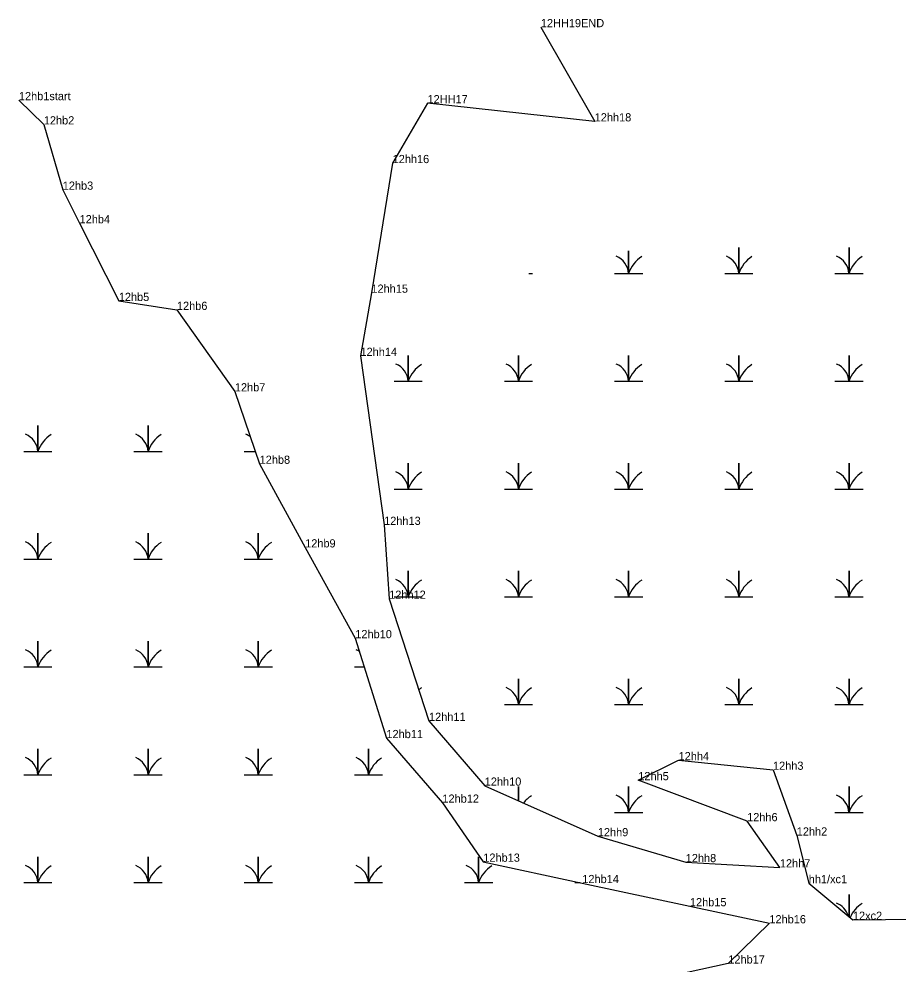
# Model space of a CAD drawing. Extents: x 2072529 to 2268796, y 436423 to 470397.
# Drawn here: x 2229917 to 2230453, y 451533 to 452110 of the extents above; entities that cross this region are included whole.
import ezdxf

# ---------------------------------------------------------------- set-up
doc = ezdxf.new("R2010")
doc.units = 0
for name, color, linetype in [('Exist Environmental Wetland Boundary', 7, 'Continuous'), ('Exist Environmental Wetland Boundary Cogo Comment', 7, 'Continuous'), ('Exist Environmental Wetland Boundary Cogo Point CELL', 7, 'Continuous'), ('Exist Hydro Swamp or Marsh', 7, 'Continuous')]:
    doc.layers.add(name, color=color, linetype=linetype)

msp = doc.modelspace()

# ---------------------------------------------------------------- linework, layer by layer
at = {"layer": 'Exist Environmental Wetland Boundary'}
for points in [[(2230235.08, 452104.53), (2230267.96, 452047.04), (2230165.91, 452058.11), (2230144.64, 452021.59), (2230131.69, 451942.48), (2230125.01, 451903.92), (2230139.43, 451800.78), (2230142.52, 451755.69), (2230166.82, 451681.15), (2230200.84, 451641.63), (2230269.85, 451610.77), (2230323.51, 451594.95), (2230380.96, 451591.75), (2230360.97, 451619.93), (2230294.56, 451644.97), (2230319.15, 451657.16), (2230376.77, 451651.31), (2230391.27, 451611.19), (2230398.58, 451582.1), (2230425.55, 451559.76), (2230485.18, 451560.46)], [(2229916.54, 452059.99), (2229931.73, 452045.2), (2229943.3, 452005.34), (2229953.58, 451984.88), (2229977.5, 451937.44), (2230012.98, 451931.99), (2230048.35, 451882.27), (2230063.46, 451838.07), (2230091.25, 451787.04), (2230121.85, 451731.65), (2230140.84, 451670.66), (2230175.01, 451631.24), (2230199.96, 451595.2), (2230260.4, 451582.17), (2230326.07, 451568.04), (2230374.56, 451557.62), (2230349.49, 451533.09), (2230284.51, 451518.88), (2230215.75, 451507.19), (2230145.13, 451476.98), (2230150.38, 451444.23)]]:
    msp.add_lwpolyline(points, dxfattribs=at)
at = {"layer": 'Exist Environmental Wetland Boundary Cogo Point CELL'}
for p, q in [((2230235.08, 452104.53), (2230235.08, 452104.53)), ((2229916.54, 452059.99), (2229916.54, 452059.99)), ((2230165.91, 452058.11), (2230165.91, 452058.11)), ((2229931.73, 452045.2), (2229931.73, 452045.2)), ((2230267.96, 452047.04), (2230267.96, 452047.04)), ((2230144.64, 452021.59), (2230144.64, 452021.59)), ((2229943.3, 452005.34), (2229943.3, 452005.34)), ((2229953.58, 451984.88), (2229953.58, 451984.88)), ((2229977.5, 451937.44), (2229977.5, 451937.44)), ((2230012.98, 451931.99), (2230012.98, 451931.99)), ((2230125.01, 451903.92), (2230125.01, 451903.92)), ((2230048.35, 451882.27), (2230048.35, 451882.27)), ((2230063.46, 451838.07), (2230063.46, 451838.07)), ((2230139.43, 451800.78), (2230139.43, 451800.78)), ((2230091.25, 451787.04), (2230091.25, 451787.04)), ((2230142.52, 451755.69), (2230142.52, 451755.69)), ((2230121.85, 451731.65), (2230121.85, 451731.65)), ((2230166.82, 451681.15), (2230166.82, 451681.15)), ((2230140.84, 451670.66), (2230140.84, 451670.66)), ((2230319.15, 451657.16), (2230319.15, 451657.16)), ((2230376.77, 451651.31), (2230376.77, 451651.31)), ((2230200.84, 451641.63), (2230200.84, 451641.63)), ((2230294.56, 451644.97), (2230294.56, 451644.97)), ((2230175.01, 451631.24), (2230175.01, 451631.24)), ((2230360.97, 451619.93), (2230360.97, 451619.93)), ((2230269.85, 451610.77), (2230269.85, 451610.77)), ((2230391.27, 451611.19), (2230391.27, 451611.19)), ((2230199.96, 451595.2), (2230199.96, 451595.2)), ((2230323.51, 451594.95), (2230323.51, 451594.95)), ((2230380.96, 451591.75), (2230380.96, 451591.75)), ((2230260.4, 451582.17), (2230260.4, 451582.17)), ((2230398.58, 451582.1), (2230398.58, 451582.1)), ((2230326.07, 451568.04), (2230326.07, 451568.04)), ((2230425.55, 451559.76), (2230425.55, 451559.76)), ((2230374.56, 451557.62), (2230374.56, 451557.62)), ((2230349.49, 451533.09), (2230349.49, 451533.09))]:
    msp.add_line(p, q, dxfattribs=at)
at = {"layer": 'Exist Hydro Swamp or Marsh'}
for points in [[(2230347.3, 451954.29), (2230355.9, 451954.29), (2230355.9, 451970.07), (2230355.9, 451954.29), (2230364.5, 451954.29)], [(2230414.55, 451954.29), (2230423.15, 451954.29), (2230423.15, 451970.07), (2230423.15, 451954.29), (2230431.75, 451954.29)], [(2230280.05, 451954.29), (2230288.65, 451954.29), (2230288.65, 451968.01)], [(2230288.65, 451968.01), (2230288.65, 451954.29), (2230297.25, 451954.29)], [(2230227.81, 451954.29), (2230230, 451954.29)], [(2230145.55, 451888.49), (2230154.15, 451888.49), (2230154.15, 451904.27), (2230154.15, 451888.49), (2230162.75, 451888.49)], [(2230212.8, 451888.49), (2230221.4, 451888.49), (2230221.4, 451904.27), (2230221.4, 451888.49), (2230230, 451888.49)], [(2230280.05, 451888.49), (2230288.65, 451888.49), (2230288.65, 451904.27), (2230288.65, 451888.49), (2230297.25, 451888.49)], [(2230347.3, 451888.49), (2230355.9, 451888.49), (2230355.9, 451904.27), (2230355.9, 451888.49), (2230364.5, 451888.49)], [(2230414.55, 451888.49), (2230423.15, 451888.49), (2230423.15, 451904.27), (2230423.15, 451888.49), (2230431.75, 451888.49)], [(2229919.53, 451845.68), (2229928.13, 451845.68), (2229928.13, 451861.46), (2229928.13, 451845.68), (2229936.73, 451845.68)], [(2229986.78, 451845.68), (2229995.38, 451845.68), (2229995.38, 451861.46), (2229995.38, 451845.68), (2230003.98, 451845.68)], [(2230054.03, 451845.68), (2230060.86, 451845.68)], [(2230145.55, 451822.69), (2230154.15, 451822.69), (2230154.15, 451838.47), (2230154.15, 451822.69), (2230162.75, 451822.69)], [(2230212.8, 451822.69), (2230221.4, 451822.69), (2230221.4, 451838.47), (2230221.4, 451822.69), (2230230, 451822.69)], [(2230280.05, 451822.69), (2230288.65, 451822.69), (2230288.65, 451838.47), (2230288.65, 451822.69), (2230297.25, 451822.69)], [(2230347.3, 451822.69), (2230355.9, 451822.69), (2230355.9, 451838.47), (2230355.9, 451822.69), (2230364.5, 451822.69)], [(2230414.55, 451822.69), (2230423.15, 451822.69), (2230423.15, 451838.47), (2230423.15, 451822.69), (2230431.75, 451822.69)], [(2229919.53, 451779.88), (2229928.13, 451779.88), (2229928.13, 451795.66), (2229928.13, 451779.88), (2229936.73, 451779.88)], [(2229986.78, 451779.88), (2229995.38, 451779.88), (2229995.38, 451795.66), (2229995.38, 451779.88), (2230003.98, 451779.88)], [(2230054.03, 451779.88), (2230062.63, 451779.88), (2230062.63, 451795.66), (2230062.63, 451779.88), (2230071.23, 451779.88)], [(2230145.55, 451756.89), (2230154.15, 451756.89), (2230154.15, 451772.67), (2230154.15, 451756.89), (2230162.75, 451756.89)], [(2230212.8, 451756.89), (2230221.4, 451756.89), (2230221.4, 451772.67), (2230221.4, 451756.89), (2230230, 451756.89)], [(2230280.05, 451756.89), (2230288.65, 451756.89), (2230288.65, 451772.67), (2230288.65, 451756.89), (2230297.25, 451756.89)], [(2230347.3, 451756.89), (2230355.9, 451756.89), (2230355.9, 451772.67), (2230355.9, 451756.89), (2230364.5, 451756.89)], [(2230414.55, 451756.89), (2230423.15, 451756.89), (2230423.15, 451772.67), (2230423.15, 451756.89), (2230431.75, 451756.89)], [(2229919.53, 451714.08), (2229928.13, 451714.08), (2229928.13, 451729.86), (2229928.13, 451714.08), (2229936.73, 451714.08)], [(2229986.78, 451714.08), (2229995.38, 451714.08), (2229995.38, 451729.86), (2229995.38, 451714.08), (2230003.98, 451714.08)], [(2230054.03, 451714.08), (2230062.63, 451714.08), (2230062.63, 451729.86), (2230062.63, 451714.08), (2230071.23, 451714.08)], [(2230121.28, 451714.08), (2230127.32, 451714.08)], [(2230212.8, 451691.09), (2230221.4, 451691.09), (2230221.4, 451706.87), (2230221.4, 451691.09), (2230230, 451691.09)], [(2230280.05, 451691.09), (2230288.65, 451691.09), (2230288.65, 451706.87), (2230288.65, 451691.09), (2230297.25, 451691.09)], [(2230347.3, 451691.09), (2230355.9, 451691.09), (2230355.9, 451706.87), (2230355.9, 451691.09), (2230364.5, 451691.09)], [(2230414.55, 451691.09), (2230423.15, 451691.09), (2230423.15, 451706.87), (2230423.15, 451691.09), (2230431.75, 451691.09)], [(2229919.53, 451648.28), (2229928.13, 451648.28), (2229928.13, 451664.06), (2229928.13, 451648.28), (2229936.73, 451648.28)], [(2229986.78, 451648.28), (2229995.38, 451648.28), (2229995.38, 451664.06), (2229995.38, 451648.28), (2230003.98, 451648.28)], [(2230054.03, 451648.28), (2230062.63, 451648.28), (2230062.63, 451664.06), (2230062.63, 451648.28), (2230071.23, 451648.28)], [(2230121.28, 451648.28), (2230129.88, 451648.28), (2230129.88, 451664.06), (2230129.88, 451648.28), (2230138.48, 451648.28)], [(2230221.4, 451632.43), (2230221.4, 451641.07), (2230221.4, 451632.43)], [(2230280.05, 451625.29), (2230288.65, 451625.29), (2230288.65, 451641.07), (2230288.65, 451625.29), (2230297.25, 451625.29)], [(2230414.55, 451625.29), (2230423.15, 451625.29), (2230423.15, 451641.07), (2230423.15, 451625.29), (2230431.75, 451625.29)], [(2229919.53, 451582.48), (2229928.13, 451582.48), (2229928.13, 451598.26), (2229928.13, 451582.48), (2229936.73, 451582.48)], [(2229986.78, 451582.48), (2229995.38, 451582.48), (2229995.38, 451598.26), (2229995.38, 451582.48), (2230003.98, 451582.48)], [(2230054.03, 451582.48), (2230062.63, 451582.48), (2230062.63, 451598.26), (2230062.63, 451582.48), (2230071.23, 451582.48)], [(2230121.28, 451582.48), (2230129.88, 451582.48), (2230129.88, 451598.26), (2230129.88, 451582.48), (2230138.48, 451582.48)], [(2230188.53, 451582.48), (2230197.13, 451582.48), (2230197.13, 451598.26), (2230197.13, 451582.48), (2230205.73, 451582.48)], [(2230255.78, 451582.48), (2230258.99, 451582.48)], [(2230423.15, 451561.75), (2230423.15, 451575.27), (2230423.15, 451561.75)]]:
    msp.add_lwpolyline(points, dxfattribs=at)
for centre, radius, start, end in [((2230276.38, 451953.4), 12.3, 4.14034, 67.53497), ((2230306.89, 451948.23), 19.22, 122.12745, 161.62219), ((2230343.63, 451953.4), 12.3, 4.14034, 67.53497), ((2230374.14, 451948.23), 19.22, 122.12745, 161.62219), ((2230410.88, 451953.4), 12.3, 4.14034, 67.53497), ((2230441.39, 451948.23), 19.22, 122.12745, 161.62219), ((2230141.88, 451887.6), 12.3, 4.14034, 67.53497), ((2230172.39, 451882.43), 19.22, 122.12745, 161.62219), ((2230209.13, 451887.6), 12.3, 4.14034, 67.53497), ((2230239.64, 451882.43), 19.22, 122.12745, 161.62219), ((2230276.38, 451887.6), 12.3, 4.14034, 67.53497), ((2230306.89, 451882.43), 19.22, 122.12745, 161.62219), ((2230343.63, 451887.6), 12.3, 4.14034, 67.53497), ((2230374.14, 451882.43), 19.22, 122.12745, 161.62219), ((2230410.88, 451887.6), 12.3, 4.14034, 67.53497), ((2230441.39, 451882.43), 19.22, 122.12745, 161.62219), ((2229915.86, 451844.79), 12.3, 4.14034, 67.53497), ((2229946.37, 451839.62), 19.22, 122.12745, 161.62219), ((2229983.11, 451844.79), 12.3, 4.14034, 67.53497), ((2230013.62, 451839.62), 19.22, 122.12745, 161.62219), ((2230050.36, 451844.79), 12.3, 52.64789, 67.53497), ((2230141.88, 451821.8), 12.3, 4.14034, 67.53497), ((2230172.39, 451816.63), 19.22, 122.12745, 161.62219), ((2230209.13, 451821.8), 12.3, 4.14034, 67.53497), ((2230239.64, 451816.63), 19.22, 122.12745, 161.62219), ((2230276.38, 451821.8), 12.3, 4.14034, 67.53497), ((2230306.89, 451816.63), 19.22, 122.12745, 161.62219), ((2230343.63, 451821.8), 12.3, 4.14034, 67.53497), ((2230374.14, 451816.63), 19.22, 122.12745, 161.62219), ((2230410.88, 451821.8), 12.3, 4.14034, 67.53497), ((2230441.39, 451816.63), 19.22, 122.12745, 161.62219), ((2229915.86, 451778.99), 12.3, 4.14034, 67.53497), ((2229983.11, 451778.99), 12.3, 4.14034, 67.53497), ((2230050.36, 451778.99), 12.3, 4.14034, 67.53497), ((2229946.37, 451773.82), 19.22, 122.12745, 161.62219), ((2230013.62, 451773.82), 19.22, 122.12745, 161.62219), ((2230080.87, 451773.82), 19.22, 122.12745, 161.62219), ((2230141.88, 451756), 12.3, 4.14034, 67.53497), ((2230209.13, 451756), 12.3, 4.14034, 67.53497), ((2230276.38, 451756), 12.3, 4.14034, 67.53497), ((2230343.63, 451756), 12.3, 4.14034, 67.53497), ((2230410.88, 451756), 12.3, 4.14034, 67.53497), ((2230172.39, 451750.83), 19.22, 122.12745, 161.62219), ((2230239.64, 451750.83), 19.22, 122.12745, 161.62219), ((2230306.89, 451750.83), 19.22, 122.12745, 161.62219), ((2230374.14, 451750.83), 19.22, 122.12745, 161.62219), ((2230441.39, 451750.83), 19.22, 122.12745, 161.62219), ((2229915.86, 451713.19), 12.3, 4.14034, 67.53497), ((2229946.37, 451708.02), 19.22, 122.12745, 161.62219), ((2229983.11, 451713.19), 12.3, 4.14034, 67.53497), ((2230013.62, 451708.02), 19.22, 122.12745, 161.62219), ((2230050.36, 451713.19), 12.3, 4.14034, 67.53497), ((2230080.87, 451708.02), 19.22, 122.12745, 161.62219), ((2230117.61, 451713.19), 12.3, 56.44243, 67.53497), ((2230172.39, 451685.03), 19.22, 122.12745, 127.82548), ((2230209.13, 451690.2), 12.3, 4.14034, 67.53497), ((2230239.64, 451685.03), 19.22, 122.12745, 161.62219), ((2230276.38, 451690.2), 12.3, 4.14034, 67.53497), ((2230306.89, 451685.03), 19.22, 122.12745, 161.62219), ((2230343.63, 451690.2), 12.3, 4.14034, 67.53497), ((2230374.14, 451685.03), 19.22, 122.12745, 161.62219), ((2230410.88, 451690.2), 12.3, 4.14034, 67.53497), ((2230441.39, 451685.03), 19.22, 122.12745, 161.62219), ((2229915.86, 451647.39), 12.3, 4.14034, 67.53497), ((2229946.37, 451642.22), 19.22, 122.12745, 161.62219), ((2229983.11, 451647.39), 12.3, 4.14034, 67.53497), ((2230013.62, 451642.22), 19.22, 122.12745, 161.62219), ((2230050.36, 451647.39), 12.3, 4.14034, 67.53497), ((2230080.87, 451642.22), 19.22, 122.12745, 161.62219), ((2230117.61, 451647.39), 12.3, 4.14034, 67.53497), ((2230148.12, 451642.22), 19.22, 122.12745, 161.62219), ((2230239.64, 451619.23), 19.22, 122.12745, 142.04224), ((2230276.38, 451624.4), 12.3, 4.14034, 67.53497), ((2230306.89, 451619.23), 19.22, 122.12745, 161.62219), ((2230410.88, 451624.4), 12.3, 4.14034, 67.53497), ((2230441.39, 451619.23), 19.22, 122.12745, 161.62219), ((2229915.86, 451581.59), 12.3, 4.14034, 67.53497), ((2229946.37, 451576.42), 19.22, 122.12745, 161.62219), ((2229983.11, 451581.59), 12.3, 4.14034, 67.53497), ((2230013.62, 451576.42), 19.22, 122.12745, 161.62219), ((2230050.36, 451581.59), 12.3, 4.14034, 67.53497), ((2230080.87, 451576.42), 19.22, 122.12745, 161.62219), ((2230117.61, 451581.59), 12.3, 4.14034, 67.53497), ((2230148.12, 451576.42), 19.22, 122.12745, 161.62219), ((2230184.86, 451581.59), 12.3, 4.14034, 67.53497), ((2230215.37, 451576.42), 19.22, 122.12745, 161.62219), ((2230410.88, 451558.6), 12.3, 16.81162, 67.53497), ((2230441.39, 451553.43), 19.22, 122.12745, 156.14785)]:
    msp.add_arc(centre, radius, start, end, dxfattribs=at)

# ---------------------------------------------------------------- texts
at = {"layer": 'Exist Environmental Wetland Boundary Cogo Comment'}
for s, p in [('12HH19END', (2230235.08, 452104.53)), ('12hb1start', (2229916.54, 452059.99)), ('12HH17', (2230165.91, 452058.11)), ('12hb2', (2229931.73, 452045.2)), ('12hh18', (2230267.96, 452047.04)), ('12hh16', (2230144.64, 452021.59)), ('12hb3', (2229943.3, 452005.34)), ('12hb4', (2229953.58, 451984.88)), ('12hh15', (2230131.69, 451942.48)), ('12hb5', (2229977.5, 451937.44)), ('12hb6', (2230012.98, 451931.99)), ('12hh14', (2230125.01, 451903.92)), ('12hb7', (2230048.35, 451882.27)), ('12hb8', (2230063.46, 451838.07)), ('12hh13', (2230139.43, 451800.78)), ('12hb9', (2230091.25, 451787.04)), ('12hh12', (2230142.52, 451755.69)), ('12hb10', (2230121.85, 451731.65)), ('12hh11', (2230166.82, 451681.15)), ('12hb11', (2230140.84, 451670.66)), ('12hh4', (2230319.15, 451657.16)), ('12hh3', (2230376.77, 451651.31)), ('12hh10', (2230200.84, 451641.63)), ('12hh5', (2230294.56, 451644.97)), ('12hb12', (2230175.01, 451631.24)), ('12hh6', (2230360.97, 451619.93)), ('12hh9', (2230269.85, 451610.77)), ('12hh2', (2230391.27, 451611.19)), ('12hb13', (2230199.96, 451595.2)), ('12hh8', (2230323.51, 451594.95)), ('12hh7', (2230380.96, 451591.75)), ('12hb14', (2230260.4, 451582.17)), ('hh1/xc1', (2230398.58, 451582.1)), ('12hb15', (2230326.07, 451568.04)), ('12hb16', (2230374.56, 451557.62)), ('12xc2', (2230425.55, 451559.76)), ('12hb17', (2230349.49, 451533.09))]:
    msp.add_text(s, height=5, dxfattribs=at).set_placement(p)

doc.saveas('drawing.dxf')
